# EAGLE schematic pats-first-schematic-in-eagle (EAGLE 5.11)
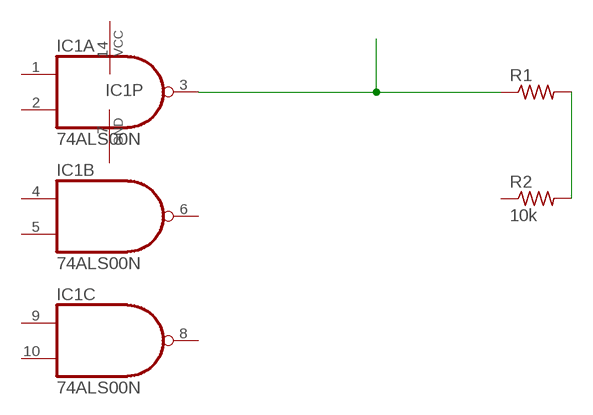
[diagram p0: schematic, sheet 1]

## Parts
IC1  74ALS00N  [DIL14]
R1  R-US_0207/10  [0207/10]
R2  10k  R-US_0207/10  [0207/10]

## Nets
N$1: R1.2 R2.2
N$2: IC1.3(A:O) R1.1
Unconnected: IC1.1(A:I0) IC1.2(A:I1) IC1.4(B:I0) IC1.5(B:I1) IC1.6(B:O) IC1.8(C:O) IC1.9(C:I0) IC1.10(C:I1) IC1.11(D:O) IC1.12(D:I0) IC1.13(D:I1) R2.1

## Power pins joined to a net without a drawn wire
GND: IC1.7(P:GND)
VCC: IC1.14(P:VCC)

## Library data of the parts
IC1 = 74xx-us:74*00: Quad 2-input NAND gate
R1 R2 = resistor:R-US_: RESISTOR, American symbol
